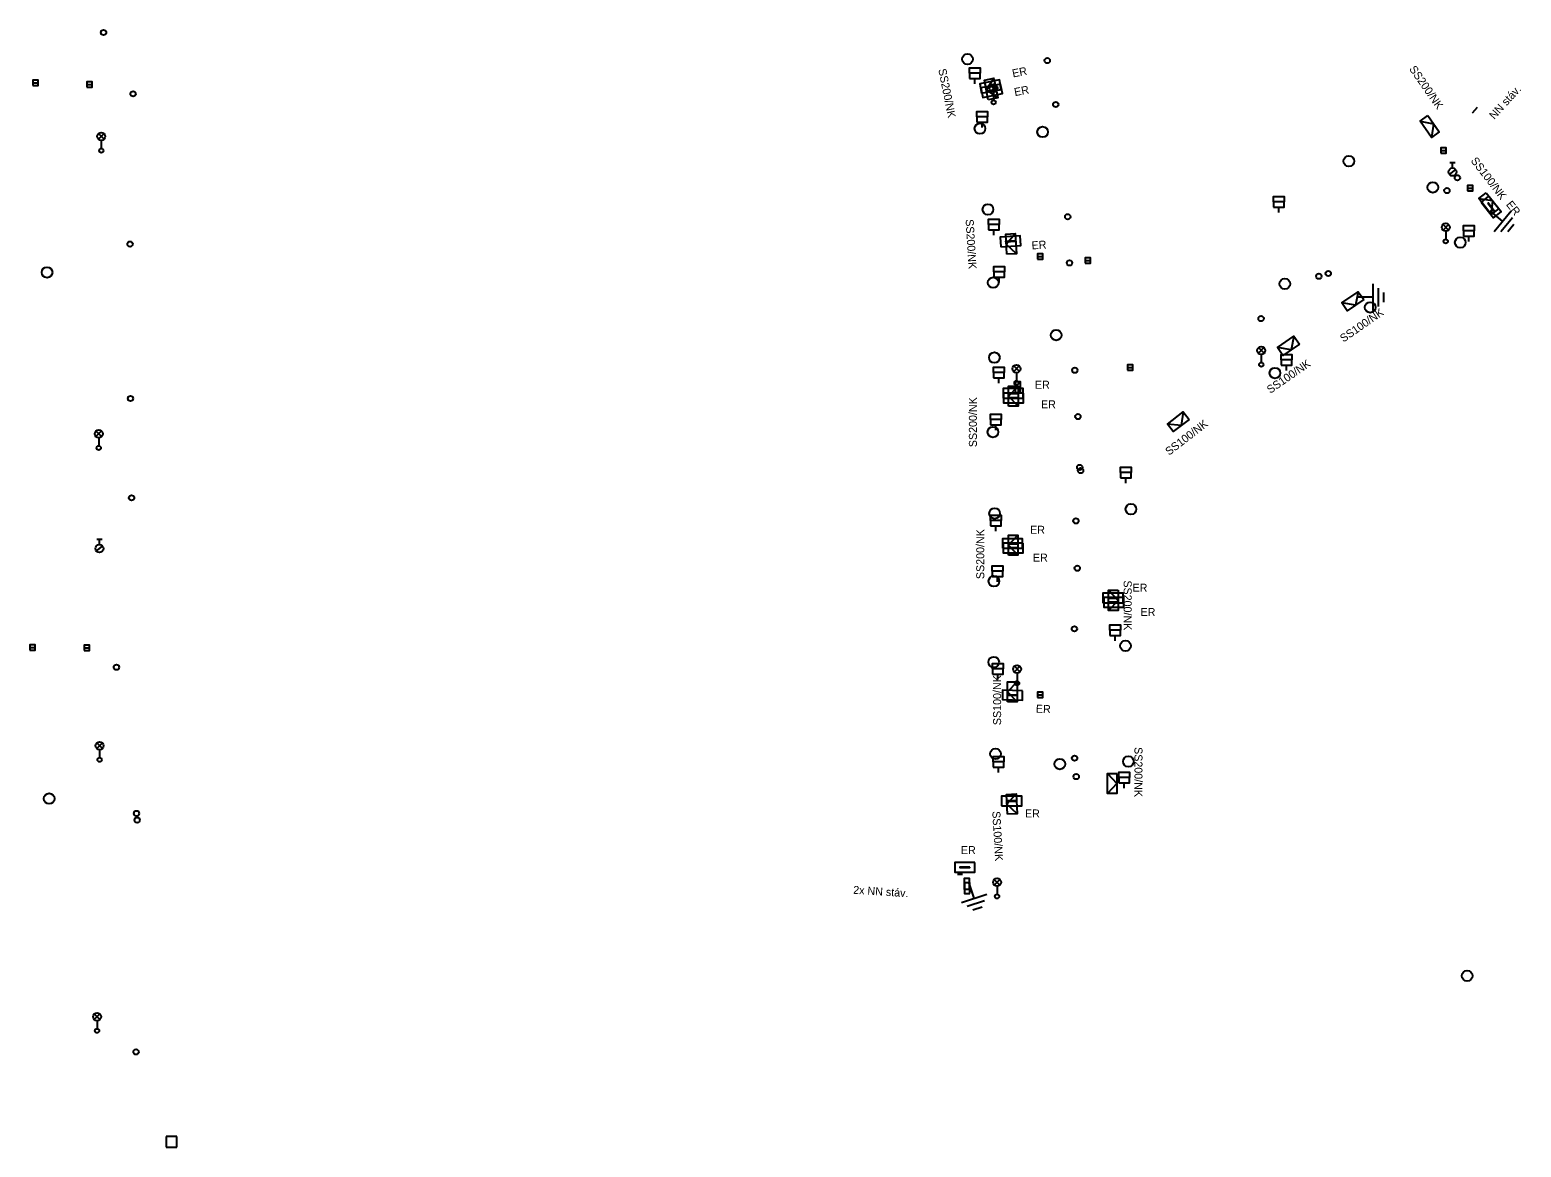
# Model space of a CAD drawing. Extents: x -584388 to -581645, y -1210859 to -1208922.
# Drawn here: x -582843.1 to -582703.3, y -1209904.9 to -1209800.1 of the extents above; entities that cross this region are included whole.
import ezdxf

# ---------------------------------------------------------------- set-up
doc = ezdxf.new("R2010")
doc.units = 0
for name, color, linetype in [('CIZÍ_NADZEM', 7, 'Continuous'), ('ELE_EON', 7, 'Continuous'), ('ELE_EON_POPIS', 7, 'Continuous')]:
    doc.layers.add(name, color=color, linetype=linetype)

msp = doc.modelspace()

# ---------------------------------------------------------------- linework, layer by layer
at = {"layer": 'CIZÍ_NADZEM'}
for p, q in [((-582842.79, -1209805.11), (-582842.29, -1209805.11)), ((-582837.75, -1209805.27), (-582837.25, -1209805.27)), ((-582754.49, -1209805.18), (-582754.49, -1209804.68)), ((-582753, -1209805.87), (-582752.48, -1209805.34)), ((-582752.47, -1209805.86), (-582753, -1209805.34)), ((-582752.74, -1209805.98), (-582752.74, -1209806.73)), ((-582836.64, -1209810.39), (-582836.12, -1209809.86)), ((-582836.11, -1209810.39), (-582836.64, -1209809.86)), ((-582753.82, -1209809.29), (-582753.82, -1209808.79)), ((-582836.38, -1209810.5), (-582836.38, -1209811.25)), ((-582710.81, -1209811.46), (-582710.31, -1209811.46)), ((-582709.98, -1209812.58), (-582709.48, -1209812.58)), ((-582709.73, -1209813.08), (-582709.73, -1209812.58)), ((-582710.02, -1209813.69), (-582709.43, -1209813.23)), ((-582708.33, -1209814.99), (-582707.83, -1209814.99)), ((-582726.02, -1209817.25), (-582726.02, -1209816.75)), ((-582752.71, -1209819.37), (-582752.71, -1209818.87)), ((-582710.62, -1209818.9), (-582710.1, -1209818.37)), ((-582710.09, -1209818.9), (-582710.62, -1209818.37)), ((-582710.36, -1209819.01), (-582710.36, -1209819.76)), ((-582708.19, -1209819.97), (-582708.19, -1209819.47)), ((-582748.62, -1209821.38), (-582748.12, -1209821.38)), ((-582744.15, -1209821.76), (-582743.65, -1209821.76)), ((-582752.23, -1209823.83), (-582752.23, -1209823.33)), ((-582727.92, -1209830.46), (-582727.4, -1209829.93)), ((-582727.39, -1209830.46), (-582727.92, -1209829.93)), ((-582727.66, -1209830.57), (-582727.66, -1209831.32)), ((-582750.86, -1209832.17), (-582750.34, -1209831.64)), ((-582750.33, -1209832.17), (-582750.86, -1209831.64)), ((-582750.6, -1209832.28), (-582750.6, -1209833.03)), ((-582740.19, -1209831.8), (-582739.69, -1209831.8)), ((-582725.29, -1209832.08), (-582725.29, -1209831.58)), ((-582752.25, -1209833.25), (-582752.25, -1209832.75)), ((-582836.88, -1209838.27), (-582836.36, -1209837.74)), ((-582836.35, -1209838.27), (-582836.88, -1209837.74)), ((-582752.52, -1209837.68), (-582752.52, -1209837.18)), ((-582836.62, -1209838.38), (-582836.62, -1209839.13)), ((-582740.35, -1209842.63), (-582740.35, -1209842.13)), ((-582752.52, -1209847.12), (-582752.52, -1209846.62)), ((-582836.85, -1209849), (-582836.26, -1209848.54)), ((-582836.81, -1209847.9), (-582836.31, -1209847.9)), ((-582836.56, -1209848.4), (-582836.56, -1209847.9)), ((-582752.37, -1209851.9), (-582752.37, -1209851.4)), ((-582741.34, -1209857.42), (-582741.34, -1209856.92)), ((-582843.08, -1209858.03), (-582842.58, -1209858.03)), ((-582838, -1209858.06), (-582837.5, -1209858.06)), ((-582750.8, -1209860.33), (-582750.28, -1209859.8)), ((-582750.27, -1209860.32), (-582750.8, -1209859.8)), ((-582752.35, -1209861.05), (-582752.35, -1209860.55)), ((-582750.54, -1209860.44), (-582750.54, -1209861.19)), ((-582748.64, -1209862.49), (-582748.14, -1209862.49)), ((-582836.8, -1209867.51), (-582836.28, -1209866.98)), ((-582836.27, -1209867.51), (-582836.8, -1209866.98)), ((-582836.54, -1209867.62), (-582836.54, -1209868.37)), ((-582752.27, -1209869.77), (-582752.27, -1209869.27)), ((-582740.51, -1209871.22), (-582740.51, -1209870.72)), ((-582752.68, -1209880.32), (-582752.16, -1209879.79)), ((-582752.15, -1209880.31), (-582752.68, -1209879.79)), ((-582752.42, -1209880.43), (-582752.42, -1209881.18)), ((-582837.04, -1209892.92), (-582836.52, -1209892.39)), ((-582836.51, -1209892.92), (-582837.04, -1209892.39)), ((-582836.78, -1209893.03), (-582836.78, -1209893.78)), ((-582829.31, -1209903.89), (-582830.31, -1209903.89)), ((-582830.31, -1209903.89), (-582830.31, -1209904.89)), ((-582830.31, -1209904.89), (-582829.31, -1209904.89)), ((-582829.31, -1209904.89), (-582829.31, -1209903.89))]:
    msp.add_line(p, q, dxfattribs=at)
for points in [[(-582754.99, -1209804.18), (-582754.99, -1209803.68), (-582753.99, -1209803.68), (-582753.99, -1209804.18)], [(-582754.32, -1209808.29), (-582754.32, -1209807.79), (-582753.32, -1209807.79), (-582753.32, -1209808.29)], [(-582726.52, -1209816.25), (-582726.52, -1209815.75), (-582725.52, -1209815.75), (-582725.52, -1209816.25)], [(-582753.21, -1209818.37), (-582753.21, -1209817.87), (-582752.21, -1209817.87), (-582752.21, -1209818.37)], [(-582708.69, -1209818.97), (-582708.69, -1209818.47), (-582707.69, -1209818.47), (-582707.69, -1209818.97)], [(-582752.73, -1209822.83), (-582752.73, -1209822.33), (-582751.73, -1209822.33), (-582751.73, -1209822.83)], [(-582725.79, -1209831.08), (-582725.79, -1209830.58), (-582724.79, -1209830.58), (-582724.79, -1209831.08)], [(-582752.75, -1209832.25), (-582752.75, -1209831.75), (-582751.75, -1209831.75), (-582751.75, -1209832.25)], [(-582753.02, -1209836.68), (-582753.02, -1209836.18), (-582752.02, -1209836.18), (-582752.02, -1209836.68)], [(-582740.85, -1209841.63), (-582740.85, -1209841.13), (-582739.85, -1209841.13), (-582739.85, -1209841.63)], [(-582753.02, -1209846.12), (-582753.02, -1209845.62), (-582752.02, -1209845.62), (-582752.02, -1209846.12)], [(-582752.87, -1209850.9), (-582752.87, -1209850.4), (-582751.87, -1209850.4), (-582751.87, -1209850.9)], [(-582741.84, -1209856.42), (-582741.84, -1209855.92), (-582740.84, -1209855.92), (-582740.84, -1209856.42)], [(-582752.85, -1209860.05), (-582752.85, -1209859.55), (-582751.85, -1209859.55), (-582751.85, -1209860.05)], [(-582752.77, -1209868.77), (-582752.77, -1209868.27), (-582751.77, -1209868.27), (-582751.77, -1209868.77)], [(-582741.01, -1209870.22), (-582741.01, -1209869.72), (-582740.01, -1209869.72), (-582740.01, -1209870.22)]]:
    msp.add_lwpolyline(points, dxfattribs=at)
for points in [[(-582754.99, -1209804.68), (-582753.99, -1209804.68), (-582753.99, -1209804.18), (-582754.99, -1209804.18)], [(-582842.79, -1209805.36), (-582842.29, -1209805.36), (-582842.29, -1209804.86), (-582842.79, -1209804.86)], [(-582837.75, -1209805.52), (-582837.25, -1209805.52), (-582837.25, -1209805.02), (-582837.75, -1209805.02)], [(-582754.32, -1209808.79), (-582753.32, -1209808.79), (-582753.32, -1209808.29), (-582754.32, -1209808.29)], [(-582710.81, -1209811.71), (-582710.31, -1209811.71), (-582710.31, -1209811.21), (-582710.81, -1209811.21)], [(-582708.33, -1209815.24), (-582707.83, -1209815.24), (-582707.83, -1209814.74), (-582708.33, -1209814.74)], [(-582726.52, -1209816.75), (-582725.52, -1209816.75), (-582725.52, -1209816.25), (-582726.52, -1209816.25)], [(-582753.21, -1209818.87), (-582752.21, -1209818.87), (-582752.21, -1209818.37), (-582753.21, -1209818.37)], [(-582708.69, -1209819.47), (-582707.69, -1209819.47), (-582707.69, -1209818.97), (-582708.69, -1209818.97)], [(-582748.62, -1209821.63), (-582748.12, -1209821.63), (-582748.12, -1209821.13), (-582748.62, -1209821.13)], [(-582744.15, -1209822.01), (-582743.65, -1209822.01), (-582743.65, -1209821.51), (-582744.15, -1209821.51)], [(-582752.73, -1209823.33), (-582751.73, -1209823.33), (-582751.73, -1209822.83), (-582752.73, -1209822.83)], [(-582752.75, -1209832.75), (-582751.75, -1209832.75), (-582751.75, -1209832.25), (-582752.75, -1209832.25)], [(-582740.19, -1209832.05), (-582739.69, -1209832.05), (-582739.69, -1209831.55), (-582740.19, -1209831.55)], [(-582725.79, -1209831.58), (-582724.79, -1209831.58), (-582724.79, -1209831.08), (-582725.79, -1209831.08)], [(-582750.22, -1209834.14), (-582750.22, -1209833.14), (-582750.72, -1209833.14), (-582750.72, -1209834.14)], [(-582753.02, -1209837.18), (-582752.02, -1209837.18), (-582752.02, -1209836.68), (-582753.02, -1209836.68)], [(-582740.85, -1209842.13), (-582739.85, -1209842.13), (-582739.85, -1209841.63), (-582740.85, -1209841.63)], [(-582753.02, -1209846.62), (-582752.02, -1209846.62), (-582752.02, -1209846.12), (-582753.02, -1209846.12)], [(-582752.87, -1209851.4), (-582751.87, -1209851.4), (-582751.87, -1209850.9), (-582752.87, -1209850.9)], [(-582741.84, -1209856.92), (-582740.84, -1209856.92), (-582740.84, -1209856.42), (-582741.84, -1209856.42)], [(-582843.08, -1209858.28), (-582842.58, -1209858.28), (-582842.58, -1209857.78), (-582843.08, -1209857.78)], [(-582838, -1209858.31), (-582837.5, -1209858.31), (-582837.5, -1209857.81), (-582838, -1209857.81)], [(-582752.85, -1209860.55), (-582751.85, -1209860.55), (-582751.85, -1209860.05), (-582752.85, -1209860.05)], [(-582748.64, -1209862.74), (-582748.14, -1209862.74), (-582748.14, -1209862.24), (-582748.64, -1209862.24)], [(-582752.77, -1209869.27), (-582751.77, -1209869.27), (-582751.77, -1209868.77), (-582752.77, -1209868.77)], [(-582741.01, -1209870.72), (-582740.01, -1209870.72), (-582740.01, -1209870.22), (-582741.01, -1209870.22)], [(-582755.01, -1209880.71), (-582755.01, -1209879.71), (-582755.51, -1209879.71), (-582755.51, -1209880.71)], [(-582754.98, -1209881.1), (-582754.98, -1209880.1), (-582755.48, -1209880.1), (-582755.48, -1209881.1)]]:
    msp.add_lwpolyline(points, close=True, dxfattribs=at)
for centre, radius in [((-582836.17, -1209800.38), 0.25), ((-582755.19, -1209802.88), 0.5), ((-582747.71, -1209803.02), 0.25), ((-582752.74, -1209805.6), 0.375), ((-582833.4, -1209806.13), 0.25), ((-582752.74, -1209806.93), 0.2), ((-582746.92, -1209807.13), 0.25), ((-582836.38, -1209810.12), 0.375), ((-582754.02, -1209809.39), 0.5), ((-582748.15, -1209809.71), 0.5), ((-582836.38, -1209811.45), 0.2), ((-582719.44, -1209812.45), 0.5), ((-582709.73, -1209813.46), 0.375), ((-582709.27, -1209814), 0.25), ((-582711.57, -1209814.9), 0.5), ((-582710.25, -1209815.21), 0.25), ((-582753.27, -1209816.97), 0.5), ((-582745.8, -1209817.65), 0.25), ((-582710.36, -1209818.64), 0.375), ((-582709, -1209820.07), 0.5), ((-582833.68, -1209820.22), 0.25), ((-582710.36, -1209819.96), 0.2), ((-582841.47, -1209822.87), 0.5), ((-582745.63, -1209821.99), 0.25), ((-582752.78, -1209823.83), 0.5), ((-582725.44, -1209823.95), 0.5), ((-582722.26, -1209823.24), 0.25), ((-582721.37, -1209822.98), 0.25), ((-582717.44, -1209826.15), 0.5), ((-582727.67, -1209827.21), 0.25), ((-582746.88, -1209828.75), 0.5), ((-582752.67, -1209830.86), 0.5), ((-582727.66, -1209830.2), 0.375), ((-582750.6, -1209831.91), 0.375), ((-582745.13, -1209832.05), 0.25), ((-582727.66, -1209831.52), 0.2), ((-582726.37, -1209832.31), 0.5), ((-582750.6, -1209833.23), 0.2), ((-582833.64, -1209834.7), 0.25), ((-582744.84, -1209836.39), 0.25), ((-582836.62, -1209838.01), 0.375), ((-582752.8, -1209837.84), 0.5), ((-582836.62, -1209839.33), 0.2), ((-582744.67, -1209841.15), 0.25), ((-582744.59, -1209841.46), 0.25), ((-582833.54, -1209844.01), 0.25), ((-582739.87, -1209845.07), 0.5), ((-582752.65, -1209845.47), 0.5), ((-582745.03, -1209846.17), 0.25), ((-582836.56, -1209848.77), 0.375), ((-582744.9, -1209850.61), 0.25), ((-582752.71, -1209851.83), 0.5), ((-582745.17, -1209856.29), 0.25), ((-582740.38, -1209857.88), 0.5), ((-582834.96, -1209859.89), 0.25), ((-582752.73, -1209859.41), 0.5), ((-582750.54, -1209860.06), 0.375), ((-582750.54, -1209861.39), 0.2), ((-582836.54, -1209867.25), 0.375), ((-582836.54, -1209868.57), 0.2), ((-582752.57, -1209868.01), 0.5), ((-582746.54, -1209868.97), 0.5), ((-582745.15, -1209868.42), 0.25), ((-582740.11, -1209868.73), 0.5), ((-582745, -1209870.15), 0.25), ((-582841.27, -1209872.21), 0.5), ((-582833.08, -1209873.6), 0.25), ((-582833.02, -1209874.22), 0.25), ((-582752.42, -1209880.05), 0.375), ((-582752.42, -1209881.38), 0.2), ((-582708.36, -1209888.82), 0.5), ((-582836.78, -1209892.66), 0.375), ((-582836.78, -1209893.98), 0.2), ((-582833.12, -1209895.96), 0.25)]:
    msp.add_circle(centre, radius, dxfattribs=at)
at = {"layer": 'ELE_EON'}
for p, q in [((-582705.04, -1209818.06), (-582706.19, -1209817.11)), ((-582705.83, -1209819.03), (-582704.24, -1209817.1)), ((-582705.19, -1209819.04), (-582704.11, -1209817.73)), ((-582704.55, -1209819.05), (-582703.98, -1209818.36)), ((-582717.18, -1209825.21), (-582718.68, -1209825.21)), ((-582717.18, -1209826.46), (-582717.18, -1209823.96)), ((-582716.68, -1209826.06), (-582716.68, -1209824.36)), ((-582716.18, -1209825.66), (-582716.18, -1209824.76)), ((-582755.75, -1209881.94), (-582753.38, -1209881.16)), ((-582754.57, -1209881.55), (-582755.04, -1209880.13)), ((-582755.22, -1209882.29), (-582753.6, -1209881.76)), ((-582754.68, -1209882.64), (-582753.83, -1209882.36))]:
    msp.add_line(p, q, dxfattribs=at)
for points in [[(-582753.87, -1209806.07), (-582752.03, -1209805.71), (-582752.2, -1209804.83), (-582754.04, -1209805.18)], [(-582752.09, -1209805.22), (-582753.93, -1209805.58), (-582753.75, -1209806.47), (-582751.91, -1209806.1)], [(-582753.24, -1209806.69), (-582753.61, -1209804.85), (-582752.73, -1209804.67), (-582752.35, -1209806.51)], [(-582753.49, -1209805.56), (-582752.57, -1209805.38), (-582752.58, -1209805.34), (-582753.5, -1209805.52)], [(-582752.47, -1209805.73), (-582753.38, -1209805.92), (-582753.38, -1209805.95), (-582752.46, -1209805.77)], [(-582712.03, -1209808.17), (-582710.97, -1209809.71), (-582711.71, -1209810.22), (-582712.77, -1209808.68)], [(-582706.56, -1209815.4), (-582705.4, -1209816.87), (-582706.11, -1209817.43), (-582707.27, -1209815.95)], [(-582707.05, -1209816.28), (-582705.89, -1209817.76), (-582705.18, -1209817.21), (-582706.34, -1209815.73)], [(-582706.42, -1209816.39), (-582705.84, -1209817.12), (-582705.81, -1209817.1), (-582706.39, -1209816.36)], [(-582752.07, -1209820.48), (-582750.19, -1209820.36), (-582750.25, -1209819.46), (-582752.12, -1209819.58)], [(-582751.51, -1209821.16), (-582751.61, -1209819.29), (-582750.71, -1209819.24), (-582750.61, -1209821.12)], [(-582751.63, -1209820.02), (-582750.69, -1209819.96), (-582750.69, -1209819.92), (-582751.63, -1209819.98)], [(-582718.05, -1209825.42), (-582719.59, -1209826.48), (-582720.1, -1209825.74), (-582718.56, -1209824.68)], [(-582724.08, -1209829.6), (-582725.62, -1209830.66), (-582726.13, -1209829.92), (-582724.59, -1209828.86)], [(-582751.35, -1209835.43), (-582751.35, -1209833.55), (-582750.45, -1209833.55), (-582750.45, -1209835.43)], [(-582751.86, -1209834.66), (-582749.98, -1209834.66), (-582749.98, -1209833.76), (-582751.86, -1209833.76)], [(-582749.93, -1209834.19), (-582751.81, -1209834.19), (-582751.81, -1209835.09), (-582749.93, -1209835.09)], [(-582751.39, -1209834.23), (-582750.45, -1209834.23), (-582750.45, -1209834.19), (-582751.39, -1209834.19)], [(-582750.4, -1209834.62), (-582751.34, -1209834.62), (-582751.34, -1209834.66), (-582750.4, -1209834.66)], [(-582734.42, -1209836.66), (-582735.9, -1209837.8), (-582736.45, -1209837.09), (-582734.97, -1209835.95)], [(-582751.36, -1209849.39), (-582751.36, -1209847.51), (-582750.46, -1209847.51), (-582750.46, -1209849.39)], [(-582751.9, -1209848.74), (-582750.02, -1209848.74), (-582750.02, -1209847.84), (-582751.9, -1209847.84)], [(-582749.97, -1209848.26), (-582751.85, -1209848.26), (-582751.85, -1209849.16), (-582749.97, -1209849.16)], [(-582751.43, -1209848.31), (-582750.49, -1209848.31), (-582750.49, -1209848.27), (-582751.43, -1209848.27)], [(-582750.44, -1209848.69), (-582751.38, -1209848.69), (-582751.38, -1209848.73), (-582750.44, -1209848.73)], [(-582742.49, -1209853.85), (-582740.61, -1209853.85), (-582740.61, -1209852.95), (-582742.49, -1209852.95)], [(-582741.08, -1209852.68), (-582741.08, -1209854.56), (-582741.98, -1209854.56), (-582741.98, -1209852.68)], [(-582740.53, -1209853.35), (-582742.41, -1209853.35), (-582742.41, -1209854.25), (-582740.53, -1209854.25)], [(-582742.02, -1209853.42), (-582741.08, -1209853.42), (-582741.08, -1209853.38), (-582742.02, -1209853.38)], [(-582741, -1209853.78), (-582741.94, -1209853.78), (-582741.94, -1209853.82), (-582741, -1209853.82)], [(-582751.44, -1209863.14), (-582751.44, -1209861.26), (-582750.54, -1209861.26), (-582750.54, -1209863.14)], [(-582750.02, -1209862.09), (-582751.9, -1209862.03), (-582751.92, -1209862.93), (-582750.05, -1209862.99)], [(-582750.5, -1209862.51), (-582751.44, -1209862.48), (-582751.44, -1209862.51), (-582750.51, -1209862.54)], [(-582741.18, -1209869.86), (-582741.18, -1209871.74), (-582742.08, -1209871.74), (-582742.08, -1209869.86)], [(-582751.99, -1209872.88), (-582750.11, -1209872.88), (-582750.11, -1209871.98), (-582751.99, -1209871.98)], [(-582751.43, -1209873.68), (-582751.54, -1209871.81), (-582750.64, -1209871.75), (-582750.54, -1209873.63)], [(-582751.52, -1209872.45), (-582750.58, -1209872.45), (-582750.58, -1209872.41), (-582751.52, -1209872.41)], [(-582754.5, -1209878.21), (-582756.38, -1209878.21), (-582756.38, -1209879.11), (-582754.5, -1209879.11)], [(-582754.97, -1209878.64), (-582755.91, -1209878.64), (-582755.91, -1209878.68), (-582754.97, -1209878.68)]]:
    msp.add_lwpolyline(points, close=True, dxfattribs=at)
for points in [[(-582752.35, -1209806.51), (-582753.42, -1209805.77), (-582752.73, -1209804.67)], [(-582707.87, -1209807.9), (-582707.4, -1209807.38)], [(-582712.77, -1209808.68), (-582711.5, -1209808.94), (-582711.71, -1209810.22)], [(-582707.27, -1209815.95), (-582705.98, -1209816.14), (-582706.11, -1209817.43)], [(-582750.61, -1209821.12), (-582751.56, -1209820.23), (-582750.71, -1209819.24)], [(-582718.56, -1209824.68), (-582718.82, -1209825.95), (-582720.1, -1209825.74)], [(-582724.59, -1209828.86), (-582724.85, -1209830.13), (-582726.13, -1209829.92)], [(-582750.45, -1209835.43), (-582751.35, -1209834.49), (-582750.45, -1209833.55)], [(-582734.97, -1209835.95), (-582735.16, -1209837.23), (-582736.45, -1209837.09)], [(-582750.46, -1209849.39), (-582751.36, -1209848.45), (-582750.46, -1209847.51)], [(-582741.98, -1209852.68), (-582741.08, -1209853.62), (-582741.98, -1209854.56)], [(-582750.54, -1209863.14), (-582751.44, -1209862.2), (-582750.54, -1209861.26)], [(-582742.08, -1209869.86), (-582741.18, -1209870.8), (-582742.08, -1209871.74)], [(-582750.54, -1209873.63), (-582751.49, -1209872.74), (-582750.64, -1209871.75)], [(-582755.66, -1209879.34), (-582756.14, -1209879.31)]]:
    msp.add_lwpolyline(points, dxfattribs=at)

# ---------------------------------------------------------------- texts
at = {"layer": 'ELE_EON_POPIS'}
for s, rotation, p in [('SS200/NK', 281.31, (-582757.93, -1209803.85)), ('ER', 11.358, (-582750.92, -1209804.6)), ('SS200/NK', 304.6952, (-582713.82, -1209803.81)), ('ER', 10.9111, (-582750.74, -1209806.35)), ('NN stáv.', 47.8913, (-582705.81, -1209808.58)), ('SS100/NK', 307.5686, (-582708.06, -1209812.42)), ('ER', 307.9716, (-582704.75, -1209816.52)), ('SS200/NK', 273.4682, (-582755.37, -1209817.91)), ('ER', 3.7357, (-582749.16, -1209820.72)), ('SS100/NK', 34.6952, (-582719.95, -1209829.46)), ('SS100/NK', 34.6952, (-582726.81, -1209834.27)), ('SS200/NK', 90, (-582754.31, -1209839.26)), ('SS100/NK', 37.5686, (-582736.29, -1209840.07)), ('SS200/NK', 90, (-582753.62, -1209851.63)), ('SS200/NK', 270, (-582740.55, -1209851.75)), ('SS100/NK', 90, (-582752.04, -1209865.32)), ('ER', 358.2415, (-582748.79, -1209864.15)), ('SS200/NK', 270, (-582739.54, -1209867.38)), ('SS100/NK', 273.3665, (-582752.87, -1209873.41)), ('2x NN stáv.', 356.4236, (-582765.92, -1209881.13))]:
    msp.add_text(s, height=0.75, rotation=rotation, dxfattribs=at).set_placement(p)
for p in [(-582748.87, -1209833.78), (-582748.3, -1209835.62), (-582749.32, -1209847.38), (-582749.06, -1209849.99), (-582739.72, -1209852.81), (-582738.97, -1209855.09), (-582749.8, -1209873.98), (-582755.81, -1209877.41)]:
    msp.add_text('ER', height=0.75, dxfattribs=at).set_placement(p)

doc.saveas('drawing.dxf')
